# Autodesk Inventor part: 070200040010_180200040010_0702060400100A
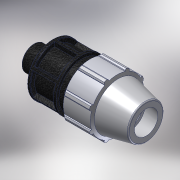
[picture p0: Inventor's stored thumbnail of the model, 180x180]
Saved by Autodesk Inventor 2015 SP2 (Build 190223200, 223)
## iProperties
Created: 2017-02
Part Number: 070200040010_180200040010_0702060400100A
Material: PVC-Piping
Description: PLASSON MALE ADAPTOR 40-1"
Document SubType Name: Modeling
Designer: KIM
Mass: 92.6774 g
Surface Area: 199.44 cm^2
Volume: 66.1981 cm^3
Density: 1.4 g/cm^3
Appearance: PTFE
Author: KIM
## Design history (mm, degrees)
derived "07020.ipt"
feature "Solid1::07020.ipt"
tag "TaggingFeature1"
body "Solid1"
other parameters: "d4" = 16.85714, "d5" = 29.5, "d7" = 82, "d8" = 61.5, "d9" = 16.85714, "d11" = 3.37143, "d12" = 65.6, "d13" = 120 deg, "d15" = 8 deg, "d16" = 73.8, "d18" = 2, "d19" = 35 deg, "d20" = 17.5 deg, "d21" = 76.26, "d23" = 0, "d25" = 360 deg, "d27" = 1.64, "d34" = 4.1, "d36" = 0, "d42" = 29.5, "d43" = 2.46, "d46" = 1.2, "d49" = 91, "d51" = 118, "d53" = 0.8, "d55" = 360 deg, "d57" = 33.249, "d58" = 23.2743, "d59" = 23.6, "E_" = 82, "H_" = 118, "l_" = 91, "R_" = 33.249
